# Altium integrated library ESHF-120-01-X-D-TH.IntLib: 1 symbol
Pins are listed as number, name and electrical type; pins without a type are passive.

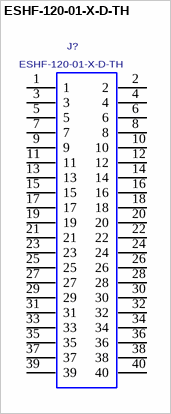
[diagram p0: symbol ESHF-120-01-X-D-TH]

## ESHF-120-01-X-D-TH
designator J?
0.05"X0.05" EXTRA LENGTH SHROUDED TERMINAL STRIP.; MANUFACTURER: SAMTEC
footprint ESHF-120-01-X-D-TH
pins: 1, 2, 3, 4, 5, 6, 7, 8, 9, 10, 11, 12, 13, 14, 15, 16, 17, 18, 19, 20, 21, 22, 23, 24, 25, 26, 27, 28, 29, 30, 31, 32, 33, 34, 35, 36, 37, 38, 39, 40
